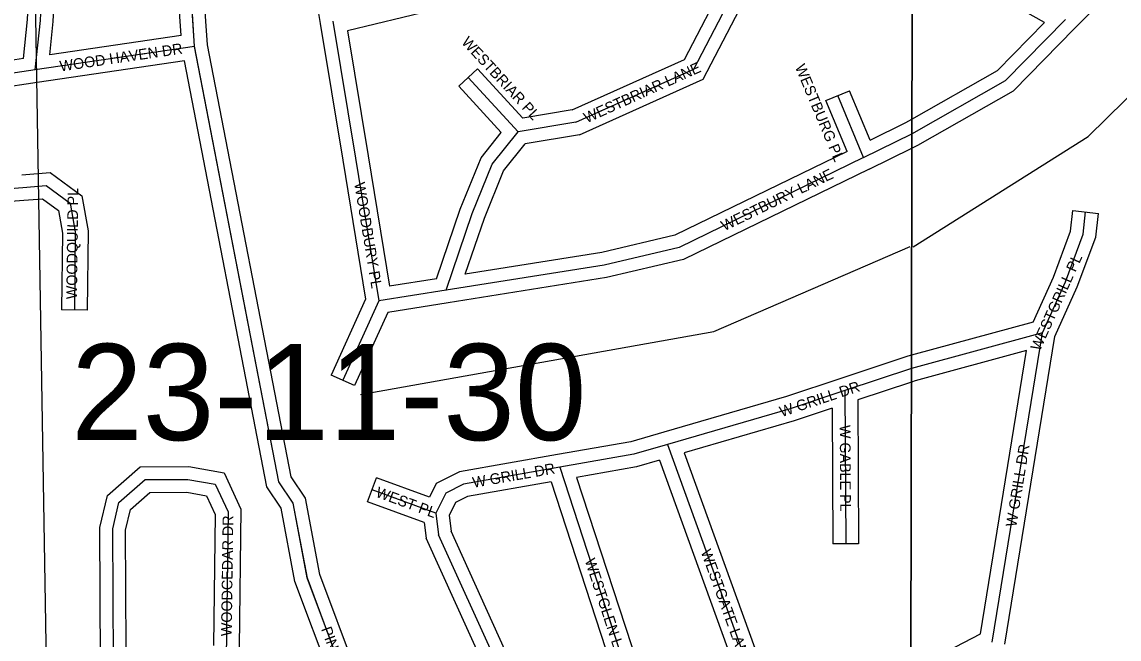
# Model space of a CAD drawing. Extents: x 457167 to 656239, y 1787309 to 1969297.
# Drawn here: x 574657 to 577222, y 1890706 to 1892149 of the extents above; entities that cross this region are included whole.
import ezdxf

# ---------------------------------------------------------------- set-up
doc = ezdxf.new("R2010")
doc.units = 0
for name, color, linetype in [('Level 1', 7, 'Continuous'), ('Level 2', 7, 'Continuous'), ('Level 31', 7, 'Continuous'), ('Level 32', 7, 'Continuous'), ('Level 34', 7, 'Continuous'), ('Level 5', 7, 'Continuous'), ('Level 63', 7, 'Continuous'), ('Level 8', 7, 'Continuous')]:
    doc.layers.add(name, color=color, linetype=linetype)

msp = doc.modelspace()

# ---------------------------------------------------------------- linework, layer by layer
at = {"layer": 'Level 1'}
msp.add_line((574767.358, 1887396.588), (574681.632, 1892654.439), dxfattribs=at)
at = {"layer": 'Level 31'}
for p, q in [((575060.629, 1892091.441), (575044.621, 1892333.297)), ((575383.854, 1892150.374), (575436.584, 1891830.619)), ((575060.629, 1892091.441), (574688.122, 1892036.983)), ((574688.122, 1892036.983), (574492.802, 1892008.321)), ((575817.057, 1891891.976), (575699.985, 1892018.777)), ((576624.354, 1891831.692), (576563.925, 1891976.551)), ((575951.94, 1891914.231), (575817.057, 1891891.976)), ((575436.584, 1891830.619), (575491.511, 1891497.041)), ((574518.631, 1891751.171), (574658.897, 1891761.771)), ((576018.003, 1891580.63), (575648.664, 1891521.792)), ((575648.664, 1891521.792), (575491.511, 1891497.041)), ((575491.511, 1891497.041), (575406.834, 1891311.041)), ((577042.617, 1891422.066), (576736.231, 1891338.731)), ((576925.001, 1890699.036), (577042.617, 1891422.066)), ((576580.892, 1891287.053), (576452.96, 1891244.781)), ((576580.892, 1891287.053), (576582.67, 1890928.863)), ((576452.96, 1891244.781), (576166.248, 1891161.033)), ((576166.248, 1891161.033), (576429.274, 1890432.823)), ((575914.264, 1891107.758), (576131.942, 1890441.826)), ((575624.636, 1891000.383), (575475.287, 1891055.253)), ((575624.636, 1891000.383), (575630.887, 1890950.187)), ((575835.355, 1890500.286), (575630.887, 1890950.187))]:
    msp.add_line(p, q, dxfattribs=at)
for points in [[(574688.122, 1892036.983), (574700.142, 1892152.594), (574706.13, 1892273.31), (574700.87, 1892339.868)], [(575951.94, 1891914.231), (576227.604, 1892038.365), (576353.1, 1892279.916)], [(576737.404, 1891887.111), (576956.103, 1892011.711), (577096.329, 1892154.322)], [(575408.201, 1890623.395), (575324.097, 1890848.671), (575291.087, 1891024.018), (575257.804, 1891073.909), (575060.629, 1892091.441)], [(575648.664, 1891521.792), (575709.791, 1891700.934), (575756.47, 1891816.107), (575817.057, 1891891.976)], [(576624.354, 1891831.692), (576737.366, 1891887.088), (576737.405, 1891887.111)], [(576624.354, 1891831.692), (576192.998, 1891621.708), (576018.003, 1891580.63)], [(574658.897, 1891761.771), (574713.923, 1891766.377), (574769.804, 1891725.528), (574781.74, 1891657.864), (574779.433, 1891475.322)], [(577042.617, 1891422.066), (577096.296, 1891541.225), (577137.557, 1891652.774), (577143.392, 1891704.762)], [(576736.232, 1891338.731), (576736.194, 1891338.721), (576580.892, 1891287.053)], [(576166.248, 1891161.033), (576087.012, 1891138.294), (575914.264, 1891107.758)], [(575914.264, 1891107.758), (575689.023, 1891068.245), (575647.954, 1891047.606), (575624.636, 1891000.383)], [(574870.809, 1890651.841), (574869.265, 1890963.847), (574883.71, 1891025.635), (574944.886, 1891078.956), (575044.745, 1891079.465), (575108.96, 1891068.051), (575138.713, 1891003.622), (575134.151, 1890662.174)]]:
    msp.add_lwpolyline(points, dxfattribs=at)
at = {"layer": 'Level 32'}
for p, q in [((577117.756, 1892133.324), (577348.282, 1892368.568)), ((575320.845, 1892346.055), (575354.261, 1892145.444)), ((575028.864, 1892117.116), (575014.814, 1892329.389)), ((577047.499, 1892147.45), (576738.335, 1892322.108)), ((575090.44, 1892095.301), (575076.37, 1892307.889)), ((575824.977, 1892226.733), (575417.984, 1892127.796)), ((575354.253, 1892145.491), (575406.984, 1891825.737)), ((575028.864, 1892117.116), (574721.951, 1892072.247)), ((575417.984, 1892127.796), (575466.185, 1891835.501)), ((574660.695, 1892063.279), (574488.446, 1892038.003)), ((575036.626, 1892057.612), (574692.462, 1892007.297)), ((575677.944, 1891998.426), (575722.028, 1892039.128)), ((575828.13, 1891924.209), (575722.028, 1892039.128)), ((574692.478, 1892007.3), (574525.518, 1891982.799)), ((575777.534, 1891890.559), (575677.944, 1891998.426)), ((576536.236, 1891965.001), (576591.613, 1891988.101)), ((576639.771, 1891872.659), (576591.613, 1891988.101)), ((576585.765, 1891846.273), (576536.236, 1891965.001)), ((575943.195, 1891943.193), (575828.13, 1891924.208)), ((575960.689, 1891885.267), (575833.31, 1891864.251)), ((576637.559, 1891804.754), (576737.334, 1891853.661)), ((575466.186, 1891835.493), (575516.274, 1891531.311)), ((575406.983, 1891825.745), (575460.428, 1891501.168)), ((574551.497, 1891723.568), (574661.159, 1891731.856)), ((577113.579, 1891708.109), (577173.205, 1891701.416)), ((576012.208, 1891610.085), (575693.147, 1891559.256)), ((575626.117, 1891548.611), (575516.274, 1891531.311)), ((576023.8, 1891551.173), (575653.384, 1891492.165)), ((575460.427, 1891501.168), (575379.53, 1891323.471)), ((574809.43, 1891474.942), (574749.435, 1891475.702)), ((575512.127, 1891469.917), (575434.139, 1891298.611)), ((575653.331, 1891492.156), (575512.127, 1891469.917)), ((577021.081, 1891447.298), (576736.298, 1891369.84)), ((576954.612, 1890694.219), (577071.594, 1891413.346)), ((576897.809, 1890718.72), (577005.524, 1891380.885)), ((575434.139, 1891298.611), (575379.53, 1891323.471)), ((576571.48, 1891315.538), (576444.045, 1891273.431)), ((576736.165, 1891307.093), (576611.001, 1891265.452)), ((576444.045, 1891273.431), (576157.836, 1891189.831)), ((576611.001, 1891265.452), (576612.67, 1890929.011)), ((576551.098, 1891245.611), (576461.875, 1891216.13)), ((576551.098, 1891245.611), (576552.67, 1890928.713)), ((576461.875, 1891216.13), (576205.314, 1891141.188)), ((576205.314, 1891141.189), (576456.132, 1890446.776)), ((576147.561, 1891124.458), (576402.417, 1890418.869)), ((575953.518, 1891084.229), (576160.459, 1890451.146)), ((575464.942, 1891027.092), (575485.634, 1891083.413)), ((575609.675, 1891037.841), (575485.634, 1891083.413)), ((575893.83, 1891073.713), (576103.427, 1890432.505)), ((575597.125, 1890978.528), (575464.942, 1891027.092)), ((575655.519, 1890995.164), (575660.094, 1890958.433)), ((575597.125, 1890978.528), (575601.683, 1890941.939)), ((575862.667, 1890512.698), (575660.094, 1890958.434)), ((575808.043, 1890487.872), (575601.683, 1890941.938)), ((576612.67, 1890929.011), (576552.67, 1890928.713)), ((576734.724, 1890634.032), (576897.809, 1890718.72))]:
    msp.add_line(p, q, dxfattribs=at)
for points in [[(574721.951, 1892072.247), (574730.066, 1892150.298), (574736.19, 1892273.75), (574730.778, 1892342.231)], [(574660.695, 1892063.279), (574670.218, 1892154.891), (574676.072, 1892272.869), (574673.436, 1892306.212)], [(575943.194, 1891943.193), (576205.785, 1892061.442), (576304.622, 1892251.676)], [(575960.69, 1891885.267), (576249.422, 1892015.288), (576371.76, 1892250.756)], [(576737.479, 1891921.681), (576937.632, 1892035.716), (577047.499, 1892147.45)], [(576737.333, 1891853.661), (576751.407, 1891860.56), (576974.573, 1891987.706), (577117.72, 1892133.287)], [(575436.306, 1890633.888), (575353.104, 1890856.751), (575319.438, 1891035.579), (575286.109, 1891085.539), (575090.44, 1892095.301)], [(575379.471, 1890614.573), (575295.091, 1890840.59), (575262.735, 1891012.456), (575229.5, 1891062.278), (575036.626, 1892057.611)], [(576639.771, 1891872.659), (576723.325, 1891913.616), (576737.48, 1891921.681)], [(575626.117, 1891548.611), (575681.671, 1891711.421), (575730.306, 1891831.419), (575777.534, 1891890.558)], [(575693.147, 1891559.256), (575737.912, 1891690.446), (575782.635, 1891800.796), (575833.31, 1891864.251)], [(576585.765, 1891846.273), (576182.88, 1891650.149), (576012.208, 1891610.085)], [(576637.485, 1891804.718), (576203.116, 1891593.266), (576023.8, 1891551.173)], [(574656.637, 1891791.686), (574722.584, 1891797.208), (574797.252, 1891742.626), (574811.774, 1891660.302), (574809.43, 1891474.942)], [(574661.4, 1891731.876), (574705.263, 1891735.546), (574742.356, 1891708.431), (574751.706, 1891655.426), (574749.435, 1891475.702)], [(577021.082, 1891447.297), (577068.519, 1891552.603), (577108.152, 1891659.753), (577113.579, 1891708.109)], [(577071.594, 1891413.346), (577124.074, 1891529.846), (577166.963, 1891645.795), (577173.205, 1891701.416)], [(576736.299, 1891369.84), (576727.515, 1891367.45), (576571.421, 1891315.52)], [(577005.524, 1891380.885), (576744.872, 1891309.991), (576736.164, 1891307.093)], [(576157.836, 1891189.831), (576080.245, 1891167.564), (575909.042, 1891137.3)], [(575909.08, 1891137.307), (575679.494, 1891097.032), (575625.503, 1891069.9), (575609.675, 1891037.841)], [(574840.808, 1890651.691), (574839.248, 1890967.234), (574856.701, 1891041.891), (574933.582, 1891108.9), (575047.315, 1891109.478), (575129.63, 1891094.849), (575168.801, 1891010.023), (575164.491, 1890687.318)], [(576147.561, 1891124.458), (576093.78, 1891109.024), (575953.517, 1891084.229)], [(575893.83, 1891073.713), (575698.552, 1891039.457), (575670.405, 1891025.312), (575655.518, 1890995.164)], [(574900.656, 1890682.981), (574899.282, 1890960.46), (574910.72, 1891009.378), (574956.191, 1891049.011), (575042.175, 1891049.451), (575088.29, 1891041.254), (575108.624, 1890997.221), (575104.532, 1890690.841)]]:
    msp.add_lwpolyline(points, dxfattribs=at)
at = {"layer": 'Level 5'}
for points in [[(576740.565, 1891623.016), (577149.298, 1891880.984), (577708.418, 1892430.6), (577950.616, 1892847.151), (578101.122, 1893280.483), (578151.529, 1893638.911), (578135.441, 1894189.115), (577861.641, 1895406.513), (577870.307, 1895706.62), (577903.974, 1896023.368), (578138.009, 1896589.983)], [(575448.277, 1891277.661), (576274.06, 1891425.065), (576733.176, 1891623.666)]]:
    msp.add_lwpolyline(points, dxfattribs=at)
at = {"layer": 'Level 63'}
for points in [[(536942.563, 1878385.707), (576708.29, 1878279.4), (576805.546, 1923734.416), (537088.612, 1923840.983), (536942.563, 1878385.707)], [(576708.289, 1878279.4), (616473.709, 1878215.526), (616521.962, 1923670.374), (576805.545, 1923734.416), (576708.289, 1878279.4)]]:
    msp.add_lwpolyline(points, dxfattribs=at)
at = {"layer": 'Level 8'}
msp.add_lwpolyline([(576730.616, 1888713.956), (576496.738, 1888877.866), (576276.73, 1889137.87), (576149.726, 1889287.871), (576017.722, 1889454.874), (575571.703, 1890255.888), (575423.696, 1890581.894), (575408.695, 1890622.895), (575323.69, 1890848.899), (575290.688, 1891023.903), (575257.686, 1891073.904), (575060.67, 1892091.926), (575044.666, 1892332.931)], dxfattribs=at)

# ---------------------------------------------------------------- texts
at = {"layer": 'Level 2'}
msp.add_text('23-11-30', height=225, dxfattribs=at).set_placement((574772.179, 1891171.197))
at = {"layer": 'Level 34'}
for s, rotation, p in [('WESTBRIAR PL', 312.714783, (575682.943, 1892100.257)), ('WOOD HAVEN DR', 8.316561, (574747.161, 1892032.982)), ('WESTBRIAR LANE', 24.241728, (575977.301, 1891911.943)), ('WESTBURG PL', 292.643467, (576463.63, 1892043.945)), ('WESTBURY LANE', 25.956083, (576299.03, 1891659.425)), ('WOODQUILD PL', 89.274858, (574785.525, 1891500.555)), ('WOODBURY PL', 279.349806, (575433.6, 1891771.815)), ('WESTGRILL PL', 65.748192, (577036.415, 1891377.869)), ('W GRILL DR', 18.283794, (576432.925, 1891224.997)), ('W GABLE PL', 270.283478, (576568.793, 1891206.636)), ('W GRILL DR', 80.759689, (576981.277, 1890967.146)), ('W GRILL DR', 9.949131, (575712.597, 1891059.69)), ('WEST PL', 339.826261, (575482.236, 1891039.385)), ('WOODCEDAR DR', 89.233956, (575147.327, 1890712.741)), ('WESTGATE LANE', 289.858881, (576243.474, 1890910.432)), ('WESTGLEN LANE', 288.100822, (575972.325, 1890889.91)), ('PINE LAKES PKWY', 290.090083, (575356.013, 1890729.691))]:
    msp.add_text(s, height=25, rotation=rotation, dxfattribs=at).set_placement(p)

doc.saveas('drawing.dxf')
